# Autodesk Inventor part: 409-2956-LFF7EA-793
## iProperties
Shininess: 64.0
Angle Display Precision: 2
Document Length Units: 11272
Document Angle Units: 11279
Document Time Units: 11290
Document Mass Units: 11286
Document Length Units Precision: 3
Document Angle Units Precision: 2
Compacted: True
Created: 2002-04
Part Number: 409-2956-LFF7EA-793
Description: 2" PIPE MOUNT ANGLE
Document SubType Name: Modeling
Designer: S. Boerckel
Mass: 2540.04 g
Surface Area: 1040.68 cm^2
Volume: 316.319 cm^3
Density: 8.03 g/cm^3
Cost Center: 3 x 3 x 1/4 ANGLE
Material: STAINLESS STEEL, 304
Engineer: S. Boerckel
Density: 0.0
Volumn: 0.0
Area: 0.0
PropertySet Name: Model Information
Control State: 0
Master: False
Checked Out: False
length: 13.500 in
SMR: =<COST CENTER> - <MATERIAL>
Author: S. Boerckel
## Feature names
1. Extrusion1
2. Hole1
